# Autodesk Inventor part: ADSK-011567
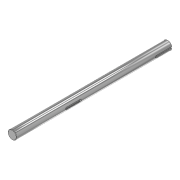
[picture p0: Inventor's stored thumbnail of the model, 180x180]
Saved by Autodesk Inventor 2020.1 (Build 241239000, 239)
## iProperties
Created: 2000-02
Part Number: ADSK-011567
Material: Pearson DGP
Description: SHFT2K,RG,CX,10,175,
Document SubType Name: Modeling
Designer: cmcgourin
Density: 7.83 g/cm^3
Appearance: Chrome - Polished
Mass: 1697.47 g
Surface Area: 363.383 cm^2
Volume: 216.791 cm^3
Control State: 0
Checked Out: False
Master: False
Shininess: 60.0
Length Units: 11269
Angle Units: 11279
Time Units: 11290
Mass Units: 11283
Length Display Precision: 3
Angle Display Precision: 2
Compacted: True
Cutlength: 17.50
Material Desc: ROUND,DGP 1144,1.0000 DIA
Material_Number: A084577
Dimensions: 25x445x25 mm
Mass: 1,697 kg
VLT_Material: Pearson DGP
DocNumber: ADSK-011567.ipt
Folder: 01 - Themengebiete\Simplification\01 - Packaging machine\
VDS_Category: 3D Komponenten
Density: 7.829999999999999
Volumn: 223.0722405291593
Area: 370.47488099996417
PropertySet Name: Model Information
Author: cmcgourin
Revision Number: -
Title: SHFT2K,RG,CX,10,175,
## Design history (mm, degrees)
node "Solide1"
  node "Extrusion1" dims "d1" = 445, "d2" = 0
  node "Chamfer1" dims "d3" = 1, "d4" = 1, "d16" = 45 deg
  node "Extrusion2" dims "d8" = 3, "d9" = 0
  node "Extrusion3" dims "d14" = 3, "d15" = 0
sketch "Sketch1"
  geometry: C1 r 12.5 at (0, 0); 1 further point
  constraints: 1 centre point, 1 coincident
  dimensions: "d0" = 25 diameter of C1
workplane "Work Plane1"
sketch "Sketch2"
  geometry: L1 (11.5, -445)-(-11.5, -445) reference; L2 (-3, -445)-(3, -445); L3 (3, -445)-(3, -400); L4 (-3, -400)-(-3, -445); L5 (0, -400)-(0, -445); A1 r 3 centre (0, -400) between (3, -400) and (-3, -400)
  constraints: 8 end point, 2 midpoint, 2 point on circle, 2 tangent, 1 centre point, 1 horizontal, 1 parallel, 1 perpendicular, 1 point on line, 1 vertical
  dimensions: "d6" = 6 distance between parallel lines of L3 L4; "d7" = 45 distance of L4.start L2.start
sketch "Sketch3"
  geometry: L1 (3.175, -143)-(3.175, -182); L2 (-2.825, -182)-(-2.825, -143); L3 (0.175, -143)-(0.175, -191.073); L4 (-11.5, 0)-(11.5, 0) reference; A1 r 3 centre (0.175, -143) between (3.175, -143) and (-2.825, -143); A2 r 3 centre (0.175, -182) between (-2.825, -182) and (3.175, -182)
  constraints: 6 end point, 4 point on circle, 4 tangent, 2 centre point, 2 vertical, 1 equal radius, 1 parallel
  dimensions: "d11" = 6 distance between parallel lines of L1 L2; "d12" = 39 distance of L2.start L2.end; "d13" = 143 distance from line of L4 L1.start
node "Corps solides"
node "Corps surfaciques"
